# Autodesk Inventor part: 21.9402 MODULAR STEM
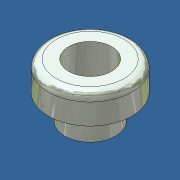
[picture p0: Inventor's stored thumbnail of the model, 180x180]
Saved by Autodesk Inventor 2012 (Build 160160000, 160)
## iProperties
Created: 2010-10
Part Number: 21.9402 MODULAR STEM
Document SubType Name: Modeling
Designer: Administrator
Density: 7.85 g/cm^3
Material: Steel
Mass: 28.0214 g
Surface Area: 24.0815 cm^2
Volume: 3.5696 cm^3
Author: Administrator
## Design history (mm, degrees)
feature "Base1"
sketch "Sketch1"
  geometry: C1 r 7.747 at (0, 0) reference; C2 r 6.541 at (0, 0) reference
extrude "Extrusion1" cut sketch "Sketch1" distance "d0" = 1.5875; taper "d1" = 0 deg
body "Solid1"
